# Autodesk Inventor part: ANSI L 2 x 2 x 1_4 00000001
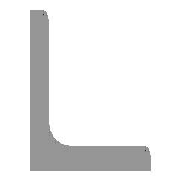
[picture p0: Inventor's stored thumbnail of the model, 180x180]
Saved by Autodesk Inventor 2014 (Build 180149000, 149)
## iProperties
_FrameMemberDoc: Frame Member File
_Version: 15.0.0
_CCFamilyMember: 11
_CCFamilyDisplayName: ANSI L (Equal angles) - Angle Steel
Created: 2007-02
Part Number: ANSI L 2 x 2 x 1_4 00000001
Material: Steel, Mild
Document SubType Name: Modeling
Standard: AISC
Designer: Autodesk, Inc.
Size Designation: L 2 x 2 x 1/4
Stock Number: L 2 x 2 x 1/4
Density: 7.86 g/cm^3
Description: Angle Steel
Standards Organization: ANSI
Language: en-US
Categories: <MemberInstance><Categories><Category DisplayName="Structural Shapes" InternalName="089c4875-fa83-4c05-b084-43b9cc11f5ed" Mnemonic="GRDR"><CategoryParameter Dis
Mass: 3582.18 g
Surface Area: 1508.05 cm^2
Volume: 455.748 cm^3
Appearance: Steel
IsCustomPart: 1
G_L: 31.000 in
G_W: 2.000 in
G_H: 2.000 in
+DBC74A79-B4E1-4546-89DD-9F49D268AF4C+CUTDETAIL1: Miter 45.00 deg
+A0A31E8A-0585-471B-91FB-4B501FC77DC9+CUTDETAIL2: Miter 45.00 deg
Author: Autodesk, Inc.
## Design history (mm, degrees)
node "Start plane"
node "End plane"
sketch "Sketch"
  geometry: L1 (50.8, 0)-(0, 0); L2 (0, 0)-(0, 50.8); L3 (0, 50.8)-(3.302, 50.8); L4 (6.35, 47.752)-(6.35, 12.7); L5 (12.7, 6.35)-(47.752, 6.35); L6 (50.8, 3.302)-(50.8, 0); L7 (0, -11.041)-(0, 31.538); L8 (-11.041, 0)-(31.538, 0); L9 (0, 63.926)-(0, -23.536) reference; L10 (-23.536, 0)-(63.926, 0) reference; A1 r 6.35 centre (12.7, 12.7) between (6.35, 12.7) and (12.7, 6.35); A2 r 3.048 centre (3.302, 47.752) between (6.35, 47.752) and (3.302, 50.8); A3 r 3.048 centre (47.752, 3.302) between (50.8, 3.302) and (47.752, 6.35); 3 further points
  constraints: 16 end point, 6 point on circle, 6 point on line, 6 tangent, 4 parallel, 3 centre point, 2 collinear, 1 equal radius, 1 horizontal, 1 perpendicular
  dimensions: "d0" = 50.8 distance between parallel lines of L6 L2 (= G_H); "d1" = 50.8 distance between parallel lines of L3 L1 (= G_H); "d2" = 6.35 distance between parallel lines of L2 L4 (= G_T); "d3" = 6.35 distance between parallel lines of L1 L5 (= G_T); "d10" = 0 distance between parallel lines of L7 L2 (computed from ex); "d11" = 0 distance between parallel lines of L8 L1 (computed from d10); "d14" = 6.35 radius of A1 (= G_IR); "d15" = 3.048 radius of A2 (= G_ER)
extrude "Body" new body sketch "Sketch" stored distance "d4" = 787.4 (= G_L); taper "d5" = 0 deg
node "Driven Length"
  sketch "Sketch4"
    geometry: L1 (0, 0)-(10, 0) reference
    constraints: 2 end point, 1 horizontal
  workplane "Work Plane5"
  sketch "Sketch5"
    geometry: L1 (-2, -6.35)-(12, -6.35) reference; L2 (-2, 781.05)-(12, 781.05) reference
    dimensions: "d19" = 787.4 distance between parallel lines of L1 L2 (derived)
workplane "Work Plane3"
split "Split1"
workplane "Work Plane4"
split "Split2"
sketch "Sketch3"
  geometry: C1 r 8.731 at (57.15, 25.4) reference; C2 r 8.731 at (260.35, 25.4) reference; C3 r 8.731 at (527.05, 25.4) reference; C4 r 8.731 at (730.25, 25.4) reference
  constraints: 4 centre point, 8 other
extrude "Extrusion2" cut sketch "Sketch3" stored distance "d16" = 25.4; taper "d17" = 0 deg
body "Solid1"
other parameters: "G_H" = 50.8 [user parameter; used in 2 equation terms], "G_T" = 6.35 [user parameter; used in 2 equation terms], "G_ER" = 3.048 [user parameter; used in 1 equation term], "G_IR" = 6.35 [user parameter; used in 1 equation term], "G_L" = 787.4 (= d19) [user parameter; used in 1 equation term], "ex" = 0 [user parameter; used in 1 equation term], "G_OFFSET_START" = 6.35 [user parameter; used in 1 equation term], "G_OFFSET_END" = 6.35 [user parameter; used in 1 equation term], "d12" = -6.35 (= -G_OFFSET_START), "d13" = 781.05 (= G_OFFSET_END + B_L), "B_L" = 774.7 [user parameter; used in 1 equation term], "d18" = 90 deg
